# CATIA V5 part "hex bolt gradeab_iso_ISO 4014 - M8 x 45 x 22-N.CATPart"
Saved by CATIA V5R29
Part number: hex bolt gradeab_iso_ISO 4014 - M8 x 45 x 22-N
Revision: HERHANG?
Definition: B??MEYEN
Nomenclature: hex bolt gradeab_iso_ISO 4014 - M8 x 45 x 22-N
Source: Unknown
Bounding box of the stored display mesh (mm): x 0 to 50.3, y -7.506 to 7.506, z -6.5 to 6.5
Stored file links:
  C:\가치같이\SmartFactory_Freeze dryer\hex bolt gradeab_iso_ISO 4014 - M8 x 45 x 22-N.CATPart
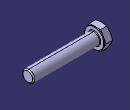
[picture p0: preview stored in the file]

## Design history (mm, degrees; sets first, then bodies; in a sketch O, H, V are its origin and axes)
Body1 "HeadFillet" (main body)
  Solid1: solid without history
